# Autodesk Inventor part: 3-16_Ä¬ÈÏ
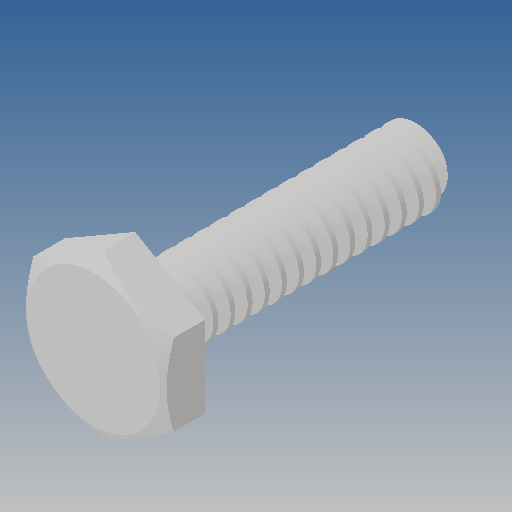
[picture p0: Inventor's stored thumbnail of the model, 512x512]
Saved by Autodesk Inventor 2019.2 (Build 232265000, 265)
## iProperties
Created: 2010-06
Part Number: 3-16_Ä¬ÈÏ
Material: Ogólny
Document SubType Name: Modeling
Designer: CADENGINEERING4
Density: 1 g/cm^3
Appearance: Domyślna
Author: CADENGINEERING4
Revision Number: ÈÎºÎ
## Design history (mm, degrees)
feature "NONE"
node "Bryła1"
